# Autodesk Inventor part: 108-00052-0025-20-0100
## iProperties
Shininess: 25.0
Created: 2003-11
Part Number: 108-00052-0025-20-0100
Description: SCR, SLTD PAN HD
Document SubType Name: Modeling
Designer: John Muchow
Material: STEEL, MILD
Engr Approved By: John M
Density: 7.860000000000001
Volumn: 0.3623567375054352
Area: 4.180399598208605
PropertySet Name: Model Information
Control State: 0
Master: False
Checked Out: False
Author: John Muchow
Revision Number: A
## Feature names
1. Revolution1
2. Extrusion1
3. Chamfer1
4. WireHole [Extrusion]
